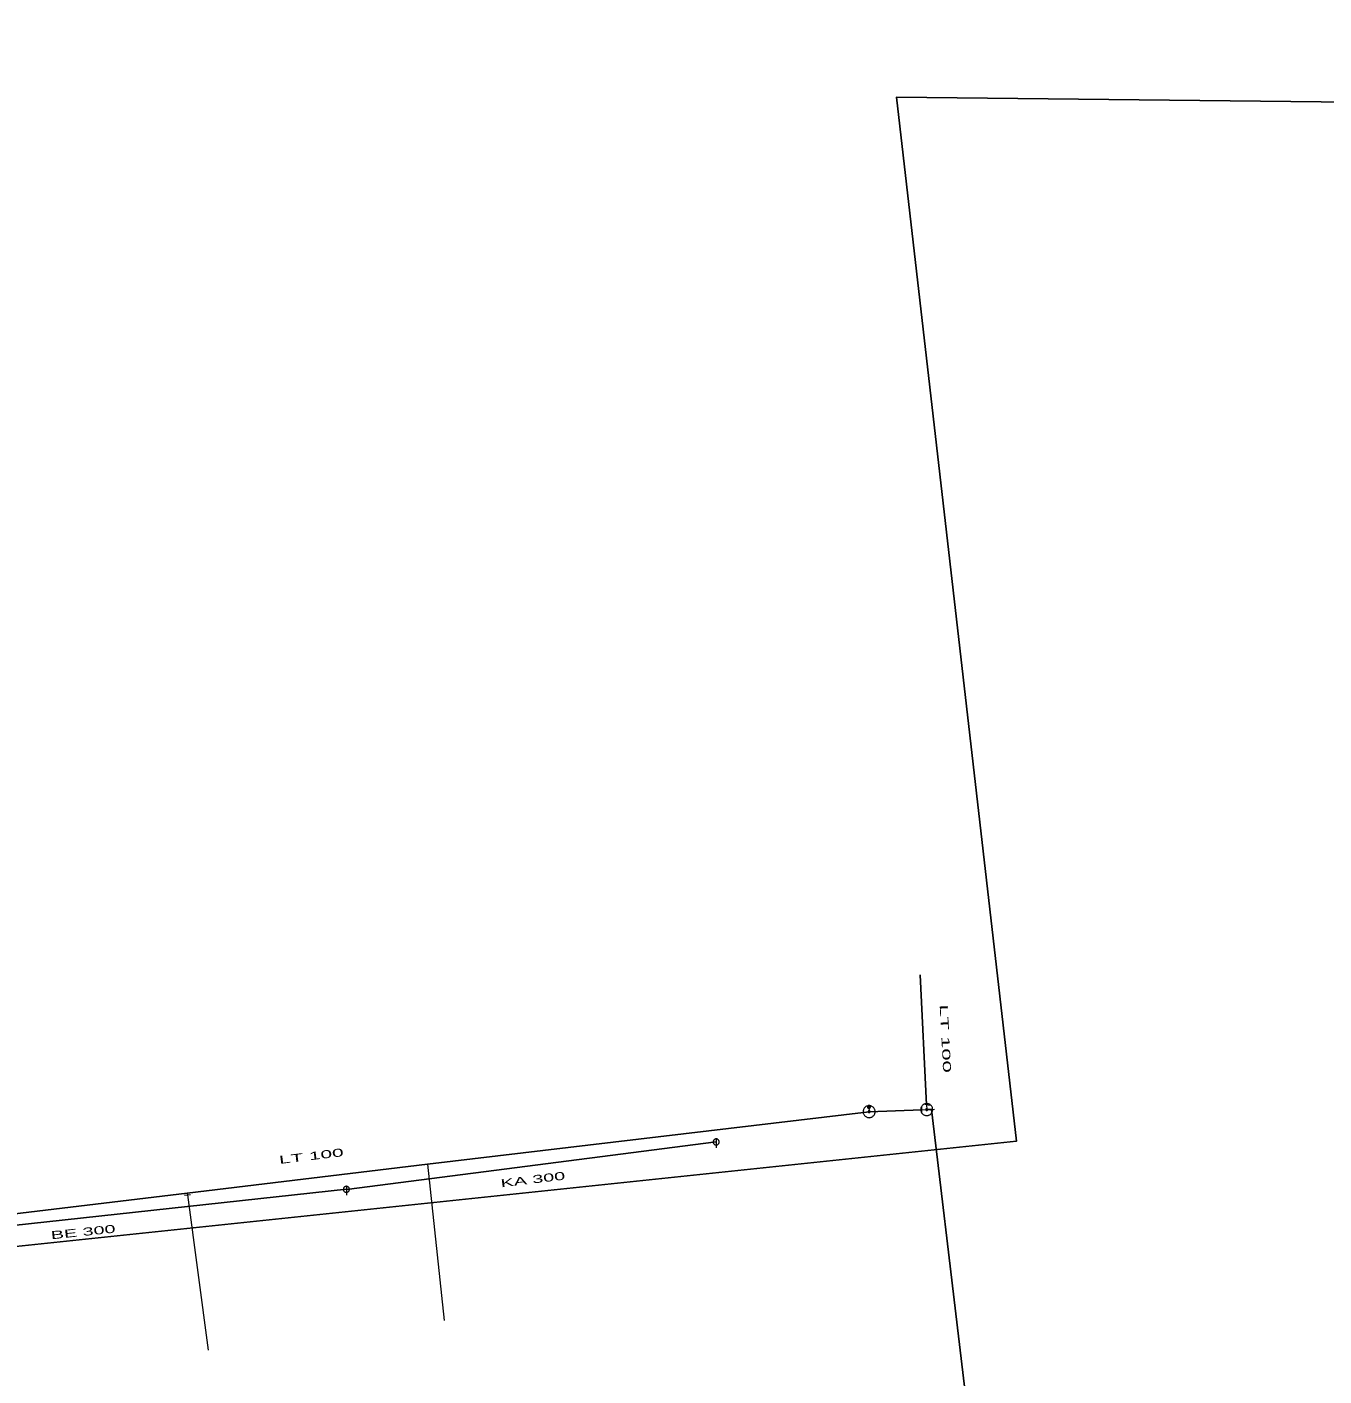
# Model space of a CAD drawing. Extents: x -687468 to -685917, y -974192 to -973456.
# Drawn here: x -686843.6 to -686735.6, y -973576.9 to -973464.5 of the extents above; entities that cross this region are included whole.
import ezdxf
from ezdxf.enums import TextEntityAlignment as Align

# ---------------------------------------------------------------- set-up
doc = ezdxf.new("R2010")
doc.units = 0
doc.header["$LTSCALE"] = 0.27
for name, color, linetype, lineweight in [('1', 7, 'Continuous', 13), ('13', 7, 'Continuous', 13), ('14', 7, 'Continuous', 25), ('17', 7, 'Continuous', 25), ('22', 7, 'Continuous', 13), ('34', 7, 'Continuous', 13), ('47', 7, 'Continuous', 13), ('9', 7, 'Continuous', 13)]:
    doc.layers.add(name, color=color, linetype=linetype, lineweight=lineweight)

msp = doc.modelspace()

# ---------------------------------------------------------------- linework, layer by layer
at = {"layer": '13'}
for p, q in [((-686810.25, -973559.235), (-686808.873, -973572.265)), ((-686830.257, -973561.773), (-686828.543, -973574.716))]:
    msp.add_line(p, q, dxfattribs=at)
at = {"layer": '14', "lineweight": 13}
for p, q in [((-686773.471, -973554.454), (-686773.456, -973554.854)), ((-686769.061, -973554.686), (-686768.661, -973554.679)), ((-686768.668, -973554.279), (-686768.661, -973554.679)), ((-686768.261, -973554.672), (-686768.661, -973554.679)), ((-686830.283, -973561.643), (-686830.257, -973561.773))]:
    msp.add_line(p, q, dxfattribs=at)
at = {"layer": '14'}
msp.add_line((-686786.202, -973557.376), (-686817.017, -973561.325), dxfattribs=at)
msp.add_lwpolyline([(-686817.017, -973561.324), (-686861.107, -973566.122), (-686910.675, -973572.458)], dxfattribs=at)
at = {"layer": '17'}
msp.add_line((-686768.668, -973554.279), (-686769.197, -973543.46), dxfattribs=at)
for points in [[(-686645.309, -973464.46), (-686646.34, -973464.75), (-686680.188, -973471.317), (-686771.188, -973470.317), (-686761.188, -973557.317), (-686894.188, -973571.317), (-686953.188, -973578.317), (-686955.188, -973554.317), (-687116.188, -973577.317), (-687229.188, -973601.317), (-687468.188, -973649.317), (-687458.188, -973700.317)], [(-686865.945, -973565.93), (-686830.283, -973561.643), (-686810.25, -973559.234), (-686773.456, -973554.854), (-686769.061, -973554.686)], [(-686760.651, -973631.405), (-686761.51, -973611.327), (-686768.261, -973554.672)]]:
    msp.add_lwpolyline(points, dxfattribs=at)
at = {"layer": '22'}
for p, q in [((-686786.201, -973557.124), (-686786.202, -973557.868)), ((-686817.016, -973561.073), (-686817.017, -973561.816))]:
    msp.add_line(p, q, dxfattribs=at)
for points in [[(-686785.95, -973557.376), (-686785.951, -973557.35), (-686785.955, -973557.324), (-686785.961, -973557.298), (-686785.971, -973557.274), (-686785.983, -973557.25), (-686785.997, -973557.228), (-686786.014, -973557.207), (-686786.032, -973557.189), (-686786.053, -973557.172), (-686786.075, -973557.158), (-686786.099, -973557.146), (-686786.123, -973557.136), (-686786.149, -973557.13), (-686786.175, -973557.126), (-686786.201, -973557.124), (-686786.227, -973557.125), (-686786.253, -973557.129), (-686786.279, -973557.135), (-686786.304, -973557.145), (-686786.327, -973557.157), (-686786.349, -973557.171), (-686786.37, -973557.188), (-686786.388, -973557.206), (-686786.405, -973557.227), (-686786.419, -973557.249), (-686786.431, -973557.273), (-686786.441, -973557.297), (-686786.448, -973557.323), (-686786.452, -973557.349), (-686786.454, -973557.375), (-686786.453, -973557.401), (-686786.449, -973557.427), (-686786.442, -973557.453), (-686786.432, -973557.478), (-686786.42, -973557.501), (-686786.406, -973557.523), (-686786.389, -973557.544), (-686786.371, -973557.562), (-686786.35, -973557.579), (-686786.328, -973557.593), (-686786.305, -973557.605), (-686786.28, -973557.615), (-686786.254, -973557.622), (-686786.228, -973557.626), (-686786.202, -973557.628), (-686786.176, -973557.627), (-686786.15, -973557.623), (-686786.124, -973557.616), (-686786.1, -973557.606), (-686786.076, -973557.594), (-686786.054, -973557.58), (-686786.033, -973557.563), (-686786.015, -973557.545), (-686785.998, -973557.524), (-686785.984, -973557.502), (-686785.972, -973557.479), (-686785.962, -973557.454), (-686785.956, -973557.428), (-686785.952, -973557.402)], [(-686816.765, -973561.325), (-686816.766, -973561.299), (-686816.77, -973561.273), (-686816.776, -973561.247), (-686816.786, -973561.223), (-686816.798, -973561.199), (-686816.812, -973561.177), (-686816.829, -973561.156), (-686816.847, -973561.138), (-686816.868, -973561.121), (-686816.89, -973561.107), (-686816.914, -973561.095), (-686816.938, -973561.085), (-686816.964, -973561.079), (-686816.99, -973561.075), (-686817.016, -973561.073), (-686817.042, -973561.074), (-686817.068, -973561.078), (-686817.094, -973561.084), (-686817.119, -973561.094), (-686817.142, -973561.106), (-686817.164, -973561.12), (-686817.185, -973561.137), (-686817.203, -973561.155), (-686817.22, -973561.176), (-686817.234, -973561.198), (-686817.246, -973561.222), (-686817.256, -973561.246), (-686817.263, -973561.272), (-686817.267, -973561.298), (-686817.269, -973561.324), (-686817.268, -973561.35), (-686817.264, -973561.376), (-686817.257, -973561.402), (-686817.247, -973561.427), (-686817.235, -973561.45), (-686817.221, -973561.472), (-686817.204, -973561.493), (-686817.186, -973561.511), (-686817.165, -973561.528), (-686817.143, -973561.542), (-686817.12, -973561.554), (-686817.095, -973561.564), (-686817.069, -973561.571), (-686817.043, -973561.575), (-686817.017, -973561.576), (-686816.991, -973561.576), (-686816.965, -973561.572), (-686816.939, -973561.565), (-686816.915, -973561.555), (-686816.891, -973561.543), (-686816.869, -973561.529), (-686816.848, -973561.512), (-686816.83, -973561.494), (-686816.813, -973561.473), (-686816.799, -973561.451), (-686816.787, -973561.428), (-686816.777, -973561.403), (-686816.771, -973561.377), (-686816.767, -973561.351)]]:
    msp.add_lwpolyline(points, close=True, dxfattribs=at)
at = {"layer": '34'}
for p, q in [((-686769.062, -973554.933), (-686769.059, -973554.438)), ((-686768.426, -973554.334), (-686768.909, -973554.223)), ((-686768.507, -973554.698), (-686768.014, -973554.645)), ((-686830.503, -973561.802), (-686830.01, -973561.743))]:
    msp.add_line(p, q, dxfattribs=at)
at = {"layer": '47'}
for points in [[(-686773.438, -973555.353), (-686773.386, -973555.348), (-686773.335, -973555.339), (-686773.285, -973555.323), (-686773.237, -973555.303), (-686773.191, -973555.278), (-686773.148, -973555.247), (-686773.109, -973555.213), (-686773.073, -973555.175), (-686773.042, -973555.133), (-686773.014, -973555.088), (-686772.992, -973555.041), (-686772.975, -973554.991), (-686772.963, -973554.941), (-686772.957, -973554.888), (-686772.956, -973554.836), (-686772.961, -973554.784), (-686772.97, -973554.733), (-686772.986, -973554.682), (-686773.006, -973554.635), (-686773.031, -973554.589), (-686773.062, -973554.546), (-686773.096, -973554.506), (-686773.134, -973554.47), (-686773.176, -973554.439), (-686773.221, -973554.412), (-686773.268, -973554.39), (-686773.318, -973554.372), (-686773.368, -973554.361), (-686773.421, -973554.355), (-686773.473, -973554.354), (-686773.525, -973554.359), (-686773.576, -973554.368), (-686773.627, -973554.383), (-686773.674, -973554.404), (-686773.72, -973554.429), (-686773.763, -973554.459), (-686773.803, -973554.493), (-686773.839, -973554.531), (-686773.87, -973554.574), (-686773.897, -973554.619), (-686773.919, -973554.666), (-686773.937, -973554.715), (-686773.948, -973554.766), (-686773.954, -973554.819), (-686773.955, -973554.871), (-686773.95, -973554.923), (-686773.941, -973554.974), (-686773.926, -973555.024), (-686773.905, -973555.072), (-686773.88, -973555.118), (-686773.85, -973555.161), (-686773.816, -973555.2), (-686773.778, -973555.236), (-686773.735, -973555.267), (-686773.69, -973555.295), (-686773.643, -973555.317), (-686773.594, -973555.334), (-686773.543, -973555.346), (-686773.49, -973555.352)], [(-686773.453, -973554.935), (-686773.444, -973554.935), (-686773.436, -973554.933), (-686773.428, -973554.931), (-686773.42, -973554.927), (-686773.412, -973554.923), (-686773.405, -973554.918), (-686773.398, -973554.913), (-686773.393, -973554.906), (-686773.388, -973554.899), (-686773.383, -973554.892), (-686773.379, -973554.884), (-686773.377, -973554.876), (-686773.375, -973554.868), (-686773.373, -973554.86), (-686773.374, -973554.851), (-686773.374, -973554.842), (-686773.376, -973554.834), (-686773.378, -973554.826), (-686773.382, -973554.818), (-686773.386, -973554.81), (-686773.391, -973554.803), (-686773.396, -973554.796), (-686773.403, -973554.791), (-686773.41, -973554.785), (-686773.417, -973554.781), (-686773.425, -973554.777), (-686773.433, -973554.775), (-686773.441, -973554.773), (-686773.449, -973554.771), (-686773.458, -973554.772), (-686773.467, -973554.772), (-686773.475, -973554.774), (-686773.483, -973554.776), (-686773.491, -973554.78), (-686773.499, -973554.784), (-686773.506, -973554.788), (-686773.513, -973554.794), (-686773.518, -973554.801), (-686773.524, -973554.808), (-686773.528, -973554.815), (-686773.532, -973554.823), (-686773.534, -973554.831), (-686773.536, -973554.839), (-686773.538, -973554.847), (-686773.537, -973554.856), (-686773.537, -973554.865), (-686773.535, -973554.873), (-686773.533, -973554.881), (-686773.529, -973554.889), (-686773.525, -973554.897), (-686773.521, -973554.904), (-686773.515, -973554.911), (-686773.508, -973554.916), (-686773.501, -973554.921), (-686773.494, -973554.926), (-686773.486, -973554.93), (-686773.478, -973554.932), (-686773.47, -973554.934), (-686773.462, -973554.936)], [(-686768.596, -973555.174), (-686768.545, -973555.165), (-686768.494, -973555.15), (-686768.446, -973555.13), (-686768.4, -973555.105), (-686768.357, -973555.076), (-686768.317, -973555.041), (-686768.281, -973555.003), (-686768.249, -973554.962), (-686768.222, -973554.918), (-686768.199, -973554.871), (-686768.181, -973554.821), (-686768.17, -973554.77), (-686768.162, -973554.719), (-686768.161, -973554.666), (-686768.165, -973554.614), (-686768.174, -973554.563), (-686768.189, -973554.512), (-686768.209, -973554.463), (-686768.234, -973554.418), (-686768.263, -973554.375), (-686768.298, -973554.335), (-686768.336, -973554.298), (-686768.377, -973554.267), (-686768.421, -973554.239), (-686768.468, -973554.217), (-686768.518, -973554.199), (-686768.569, -973554.187), (-686768.62, -973554.18), (-686768.673, -973554.179), (-686768.725, -973554.183), (-686768.776, -973554.192), (-686768.827, -973554.207), (-686768.876, -973554.226), (-686768.921, -973554.252), (-686768.964, -973554.281), (-686769.004, -973554.315), (-686769.041, -973554.353), (-686769.073, -973554.394), (-686769.1, -973554.439), (-686769.122, -973554.486), (-686769.14, -973554.536), (-686769.153, -973554.586), (-686769.159, -973554.638), (-686769.16, -973554.691), (-686769.156, -973554.743), (-686769.147, -973554.794), (-686769.132, -973554.845), (-686769.113, -973554.893), (-686769.087, -973554.939), (-686769.058, -973554.982), (-686769.024, -973555.022), (-686768.986, -973555.058), (-686768.945, -973555.09), (-686768.9, -973555.117), (-686768.853, -973555.14), (-686768.803, -973555.158), (-686768.753, -973555.17), (-686768.701, -973555.177), (-686768.648, -973555.178)], [(-686768.65, -973554.76), (-686768.641, -973554.759), (-686768.633, -973554.756), (-686768.626, -973554.753), (-686768.618, -973554.749), (-686768.611, -973554.744), (-686768.604, -973554.738), (-686768.598, -973554.732), (-686768.593, -973554.725), (-686768.589, -973554.718), (-686768.585, -973554.71), (-686768.582, -973554.702), (-686768.58, -973554.693), (-686768.579, -973554.685), (-686768.578, -973554.677), (-686768.579, -973554.668), (-686768.58, -973554.659), (-686768.583, -973554.651), (-686768.586, -973554.644), (-686768.59, -973554.636), (-686768.595, -973554.629), (-686768.601, -973554.622), (-686768.607, -973554.616), (-686768.614, -973554.611), (-686768.622, -973554.606), (-686768.629, -973554.603), (-686768.637, -973554.6), (-686768.646, -973554.598), (-686768.654, -973554.597), (-686768.662, -973554.596), (-686768.671, -973554.597), (-686768.68, -973554.598), (-686768.688, -973554.601), (-686768.695, -973554.604), (-686768.703, -973554.608), (-686768.71, -973554.613), (-686768.717, -973554.618), (-686768.723, -973554.625), (-686768.728, -973554.632), (-686768.733, -973554.64), (-686768.736, -973554.647), (-686768.739, -973554.655), (-686768.741, -973554.664), (-686768.742, -973554.672), (-686768.743, -973554.68), (-686768.742, -973554.689), (-686768.741, -973554.698), (-686768.738, -973554.706), (-686768.735, -973554.713), (-686768.731, -973554.721), (-686768.726, -973554.728), (-686768.721, -973554.735), (-686768.714, -973554.741), (-686768.707, -973554.746), (-686768.7, -973554.75), (-686768.692, -973554.754), (-686768.684, -973554.757), (-686768.675, -973554.759), (-686768.667, -973554.76), (-686768.659, -973554.761)]]:
    msp.add_lwpolyline(points, close=True, dxfattribs=at)
at = {"layer": '9'}
for points in [[(-686773.345, -973554.454), (-686773.346, -973554.441), (-686773.348, -973554.428), (-686773.351, -973554.415), (-686773.356, -973554.403), (-686773.362, -973554.391), (-686773.369, -973554.38), (-686773.377, -973554.37), (-686773.387, -973554.36), (-686773.397, -973554.352), (-686773.408, -973554.345), (-686773.42, -973554.339), (-686773.432, -973554.334), (-686773.445, -973554.331), (-686773.458, -973554.329), (-686773.471, -973554.328), (-686773.484, -973554.329), (-686773.497, -973554.331), (-686773.51, -973554.334), (-686773.522, -973554.339), (-686773.534, -973554.345), (-686773.545, -973554.352), (-686773.555, -973554.36), (-686773.565, -973554.37), (-686773.573, -973554.38), (-686773.58, -973554.391), (-686773.586, -973554.403), (-686773.591, -973554.415), (-686773.594, -973554.428), (-686773.596, -973554.441), (-686773.597, -973554.454), (-686773.596, -973554.467), (-686773.594, -973554.48), (-686773.591, -973554.493), (-686773.586, -973554.505), (-686773.58, -973554.517), (-686773.573, -973554.528), (-686773.565, -973554.538), (-686773.555, -973554.548), (-686773.545, -973554.556), (-686773.534, -973554.563), (-686773.522, -973554.569), (-686773.51, -973554.574), (-686773.497, -973554.577), (-686773.484, -973554.579), (-686773.471, -973554.58), (-686773.458, -973554.579), (-686773.445, -973554.577), (-686773.432, -973554.574), (-686773.42, -973554.569), (-686773.408, -973554.563), (-686773.397, -973554.556), (-686773.387, -973554.548), (-686773.377, -973554.538), (-686773.369, -973554.528), (-686773.362, -973554.517), (-686773.356, -973554.505), (-686773.351, -973554.493), (-686773.348, -973554.48), (-686773.346, -973554.467)], [(-686773.365, -973554.454), (-686773.365, -973554.443), (-686773.367, -973554.432), (-686773.37, -973554.421), (-686773.374, -973554.411), (-686773.379, -973554.401), (-686773.385, -973554.392), (-686773.392, -973554.383), (-686773.4, -973554.375), (-686773.409, -973554.368), (-686773.418, -973554.362), (-686773.428, -973554.357), (-686773.438, -973554.353), (-686773.449, -973554.35), (-686773.46, -973554.348), (-686773.471, -973554.348), (-686773.482, -973554.348), (-686773.493, -973554.35), (-686773.504, -973554.353), (-686773.514, -973554.357), (-686773.524, -973554.362), (-686773.533, -973554.368), (-686773.542, -973554.375), (-686773.55, -973554.383), (-686773.557, -973554.392), (-686773.563, -973554.401), (-686773.568, -973554.411), (-686773.572, -973554.421), (-686773.575, -973554.432), (-686773.577, -973554.443), (-686773.577, -973554.454), (-686773.577, -973554.465), (-686773.575, -973554.476), (-686773.572, -973554.487), (-686773.568, -973554.497), (-686773.563, -973554.507), (-686773.557, -973554.516), (-686773.55, -973554.525), (-686773.542, -973554.533), (-686773.533, -973554.54), (-686773.524, -973554.546), (-686773.514, -973554.551), (-686773.504, -973554.555), (-686773.493, -973554.558), (-686773.482, -973554.56), (-686773.471, -973554.56), (-686773.46, -973554.56), (-686773.449, -973554.558), (-686773.438, -973554.555), (-686773.428, -973554.551), (-686773.418, -973554.546), (-686773.409, -973554.54), (-686773.4, -973554.533), (-686773.392, -973554.525), (-686773.385, -973554.516), (-686773.379, -973554.507), (-686773.374, -973554.497), (-686773.37, -973554.487), (-686773.367, -973554.476), (-686773.365, -973554.465)], [(-686773.384, -973554.454), (-686773.385, -973554.445), (-686773.386, -973554.436), (-686773.389, -973554.427), (-686773.392, -973554.419), (-686773.396, -973554.411), (-686773.401, -973554.403), (-686773.407, -973554.396), (-686773.413, -973554.39), (-686773.42, -973554.384), (-686773.428, -973554.379), (-686773.436, -973554.375), (-686773.444, -973554.372), (-686773.453, -973554.369), (-686773.462, -973554.368), (-686773.471, -973554.367), (-686773.48, -973554.368), (-686773.489, -973554.369), (-686773.498, -973554.372), (-686773.506, -973554.375), (-686773.514, -973554.379), (-686773.522, -973554.384), (-686773.529, -973554.39), (-686773.535, -973554.396), (-686773.541, -973554.403), (-686773.546, -973554.411), (-686773.55, -973554.419), (-686773.553, -973554.427), (-686773.556, -973554.436), (-686773.557, -973554.445), (-686773.558, -973554.454), (-686773.557, -973554.463), (-686773.556, -973554.472), (-686773.553, -973554.481), (-686773.55, -973554.489), (-686773.546, -973554.497), (-686773.541, -973554.505), (-686773.535, -973554.512), (-686773.529, -973554.518), (-686773.522, -973554.524), (-686773.514, -973554.529), (-686773.506, -973554.533), (-686773.498, -973554.536), (-686773.489, -973554.539), (-686773.48, -973554.54), (-686773.471, -973554.541), (-686773.462, -973554.54), (-686773.453, -973554.539), (-686773.444, -973554.536), (-686773.436, -973554.533), (-686773.428, -973554.529), (-686773.42, -973554.524), (-686773.413, -973554.518), (-686773.407, -973554.512), (-686773.401, -973554.505), (-686773.396, -973554.497), (-686773.392, -973554.489), (-686773.389, -973554.481), (-686773.386, -973554.472), (-686773.385, -973554.463)], [(-686773.404, -973554.454), (-686773.404, -973554.447), (-686773.406, -973554.44), (-686773.407, -973554.433), (-686773.41, -973554.427), (-686773.413, -973554.421), (-686773.417, -973554.415), (-686773.421, -973554.409), (-686773.426, -973554.404), (-686773.432, -973554.4), (-686773.438, -973554.396), (-686773.444, -973554.393), (-686773.45, -973554.39), (-686773.457, -973554.389), (-686773.464, -973554.387), (-686773.471, -973554.387), (-686773.478, -973554.387), (-686773.485, -973554.389), (-686773.492, -973554.39), (-686773.498, -973554.393), (-686773.505, -973554.396), (-686773.51, -973554.4), (-686773.516, -973554.404), (-686773.521, -973554.409), (-686773.525, -973554.415), (-686773.529, -973554.421), (-686773.532, -973554.427), (-686773.535, -973554.433), (-686773.537, -973554.44), (-686773.538, -973554.447), (-686773.538, -973554.454), (-686773.538, -973554.461), (-686773.537, -973554.468), (-686773.535, -973554.475), (-686773.532, -973554.481), (-686773.529, -973554.488), (-686773.525, -973554.493), (-686773.521, -973554.499), (-686773.516, -973554.504), (-686773.51, -973554.508), (-686773.505, -973554.512), (-686773.498, -973554.515), (-686773.492, -973554.518), (-686773.485, -973554.52), (-686773.478, -973554.521), (-686773.471, -973554.521), (-686773.464, -973554.521), (-686773.457, -973554.52), (-686773.45, -973554.518), (-686773.444, -973554.515), (-686773.438, -973554.512), (-686773.432, -973554.508), (-686773.426, -973554.504), (-686773.421, -973554.499), (-686773.417, -973554.493), (-686773.413, -973554.488), (-686773.41, -973554.481), (-686773.407, -973554.475), (-686773.406, -973554.468), (-686773.404, -973554.461)], [(-686773.424, -973554.454), (-686773.424, -973554.449), (-686773.425, -973554.444), (-686773.426, -973554.439), (-686773.428, -973554.435), (-686773.43, -973554.43), (-686773.433, -973554.426), (-686773.436, -973554.423), (-686773.44, -973554.419), (-686773.443, -973554.416), (-686773.447, -973554.413), (-686773.452, -973554.411), (-686773.456, -973554.409), (-686773.461, -973554.408), (-686773.466, -973554.407), (-686773.471, -973554.407), (-686773.476, -973554.407), (-686773.481, -973554.408), (-686773.486, -973554.409), (-686773.49, -973554.411), (-686773.495, -973554.413), (-686773.499, -973554.416), (-686773.503, -973554.419), (-686773.506, -973554.423), (-686773.509, -973554.426), (-686773.512, -973554.43), (-686773.514, -973554.435), (-686773.516, -973554.439), (-686773.517, -973554.444), (-686773.518, -973554.449), (-686773.518, -973554.454), (-686773.518, -973554.459), (-686773.517, -973554.464), (-686773.516, -973554.469), (-686773.514, -973554.473), (-686773.512, -973554.478), (-686773.509, -973554.482), (-686773.506, -973554.486), (-686773.503, -973554.489), (-686773.499, -973554.492), (-686773.495, -973554.495), (-686773.49, -973554.497), (-686773.486, -973554.499), (-686773.481, -973554.5), (-686773.476, -973554.501), (-686773.471, -973554.501), (-686773.466, -973554.501), (-686773.461, -973554.5), (-686773.456, -973554.499), (-686773.452, -973554.497), (-686773.447, -973554.495), (-686773.443, -973554.492), (-686773.44, -973554.489), (-686773.436, -973554.486), (-686773.433, -973554.482), (-686773.43, -973554.478), (-686773.428, -973554.473), (-686773.426, -973554.469), (-686773.425, -973554.464), (-686773.424, -973554.459)], [(-686773.444, -973554.454), (-686773.444, -973554.451), (-686773.444, -973554.448), (-686773.445, -973554.446), (-686773.446, -973554.443), (-686773.447, -973554.44), (-686773.449, -973554.438), (-686773.451, -973554.436), (-686773.453, -973554.434), (-686773.455, -973554.432), (-686773.457, -973554.43), (-686773.46, -973554.429), (-686773.463, -973554.428), (-686773.465, -973554.427), (-686773.468, -973554.427), (-686773.471, -973554.427), (-686773.474, -973554.427), (-686773.477, -973554.427), (-686773.48, -973554.428), (-686773.482, -973554.429), (-686773.485, -973554.43), (-686773.487, -973554.432), (-686773.49, -973554.434), (-686773.492, -973554.436), (-686773.493, -973554.438), (-686773.495, -973554.44), (-686773.496, -973554.443), (-686773.497, -973554.446), (-686773.498, -973554.448), (-686773.498, -973554.451), (-686773.499, -973554.454), (-686773.498, -973554.457), (-686773.498, -973554.46), (-686773.497, -973554.463), (-686773.496, -973554.465), (-686773.495, -973554.468), (-686773.493, -973554.47), (-686773.492, -973554.473), (-686773.49, -973554.475), (-686773.487, -973554.476), (-686773.485, -973554.478), (-686773.482, -973554.479), (-686773.48, -973554.48), (-686773.477, -973554.481), (-686773.474, -973554.481), (-686773.471, -973554.482), (-686773.468, -973554.481), (-686773.465, -973554.481), (-686773.463, -973554.48), (-686773.46, -973554.479), (-686773.457, -973554.478), (-686773.455, -973554.476), (-686773.453, -973554.475), (-686773.451, -973554.473), (-686773.449, -973554.47), (-686773.447, -973554.468), (-686773.446, -973554.465), (-686773.445, -973554.463), (-686773.444, -973554.46), (-686773.444, -973554.457)], [(-686773.463, -973554.454), (-686773.463, -973554.453), (-686773.463, -973554.452), (-686773.464, -973554.452), (-686773.464, -973554.451), (-686773.464, -973554.45), (-686773.465, -973554.449), (-686773.465, -973554.449), (-686773.466, -973554.448), (-686773.466, -973554.448), (-686773.467, -973554.447), (-686773.468, -973554.447), (-686773.469, -973554.447), (-686773.469, -973554.446), (-686773.47, -973554.446), (-686773.471, -973554.446), (-686773.472, -973554.446), (-686773.473, -973554.446), (-686773.473, -973554.447), (-686773.474, -973554.447), (-686773.475, -973554.447), (-686773.476, -973554.448), (-686773.476, -973554.448), (-686773.477, -973554.449), (-686773.477, -973554.449), (-686773.478, -973554.45), (-686773.478, -973554.451), (-686773.479, -973554.452), (-686773.479, -973554.452), (-686773.479, -973554.453), (-686773.479, -973554.454), (-686773.479, -973554.455), (-686773.479, -973554.456), (-686773.479, -973554.456), (-686773.478, -973554.457), (-686773.478, -973554.458), (-686773.477, -973554.459), (-686773.477, -973554.459), (-686773.476, -973554.46), (-686773.476, -973554.46), (-686773.475, -973554.461), (-686773.474, -973554.461), (-686773.473, -973554.462), (-686773.473, -973554.462), (-686773.472, -973554.462), (-686773.471, -973554.462), (-686773.47, -973554.462), (-686773.469, -973554.462), (-686773.469, -973554.462), (-686773.468, -973554.461), (-686773.467, -973554.461), (-686773.466, -973554.46), (-686773.466, -973554.46), (-686773.465, -973554.459), (-686773.465, -973554.459), (-686773.464, -973554.458), (-686773.464, -973554.457), (-686773.464, -973554.456), (-686773.463, -973554.456), (-686773.463, -973554.455)]]:
    msp.add_lwpolyline(points, close=True, dxfattribs=at)

# ---------------------------------------------------------------- texts
at = {"layer": '1'}
for s, rotation, width, p in [('LT 100', 273, 2.05, (-686767.431, -973548.784)), ('LT 100', 7, 1.95, (-686819.901, -973558.881)), ('KA 300', 7, 1.85, (-686801.438, -973560.834)), ('BE 300', 6, 1.85, (-686838.919, -973565.208))]:
    msp.add_text(s, height=0.6667, rotation=rotation, dxfattribs=dict(at, width=width)).set_placement(p, align=Align.CENTER)

doc.saveas('drawing.dxf')
